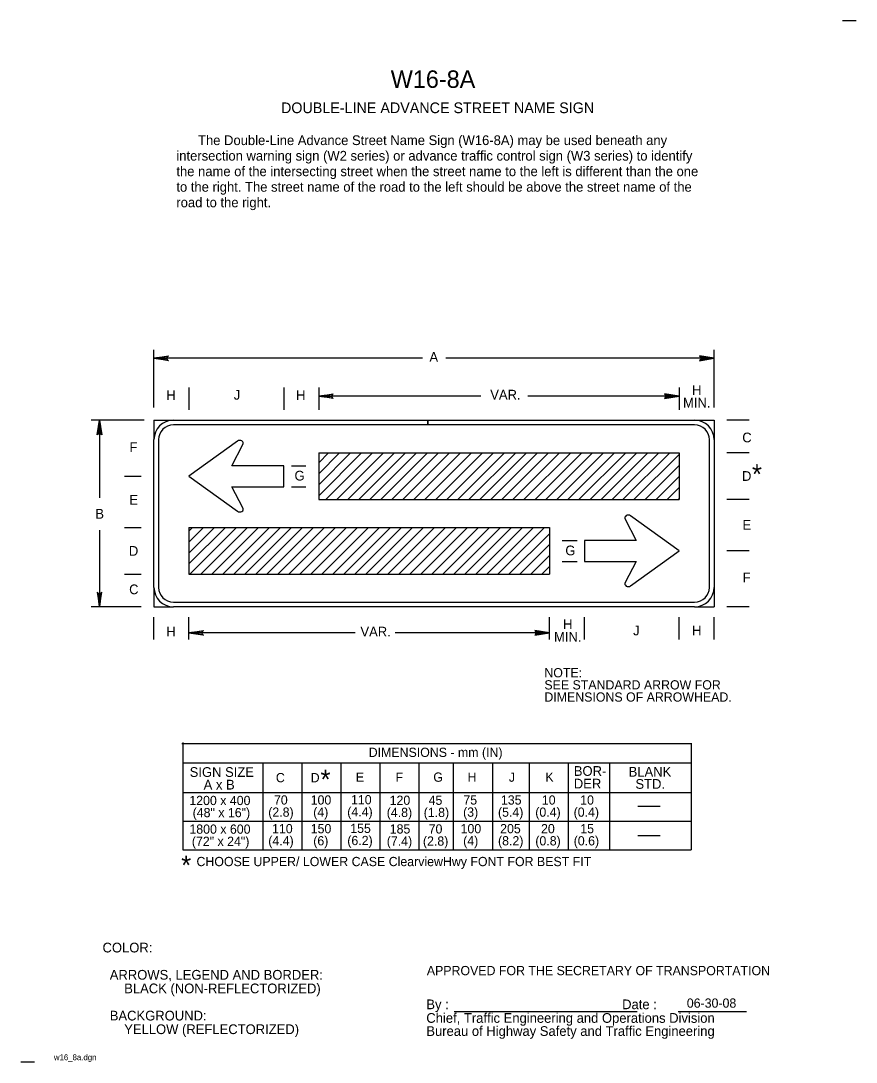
# Model space of a CAD drawing. Extents: x 0.004 to 0.219, y 0.004 to 0.272.
import ezdxf

# ---------------------------------------------------------------- set-up
doc = ezdxf.new("R2010")
doc.units = 0
for name, color, linetype in [('1', 7, 'Continuous'), ('2', 7, 'Continuous'), ('3', 7, 'Continuous'), ('4', 7, 'Continuous'), ('63', 7, 'Continuous')]:
    doc.layers.add(name, color=color, linetype=linetype)

# ---------------------------------------------------------------- blocks, each defined once
blk = doc.blocks.new('RARROW')
at = {"layer": '3'}
for p, q in [((-2.156, 0.285), (-2.2665, 0.384625)), ((-2.2665, 0.384625), (0, 0)), ((0, 0), (-2.2665, -0.379125)), ((-2.156, 0.285), (-2.075625, 0.12075)), ((0, 0), (-2.156, 0.285)), ((-2.14975, -0.2705), (0, 0)), ((-2.075625, 0.12075), (0, 0)), ((0, 0), (-2.074, -0.108)), ((-2.2665, -0.379125), (-2.14975, -0.2705)), ((-2.074, -0.108), (-2.14975, -0.2705))]:
    blk.add_line(p, q, dxfattribs=at)

msp = doc.modelspace()

# ---------------------------------------------------------------- linework, layer by layer
at = {"layer": '1'}
for p, q in [((0.04735, 0.17742), (0.04735, 0.1717)), ((0.0717, 0.17742), (0.0717, 0.1717)), ((0.0807, 0.17742), (0.0807, 0.1717)), ((0.17335, 0.17742), (0.17335, 0.1717)), ((0.02436, 0.16901), (0.02436, 0.14904)), ((0.03835, 0.16901), (0.03835, 0.16401)), ((0.04335, 0.16901), (0.10877, 0.16901)), ((0.10877, 0.16901), (0.10877, 0.16781)), ((0.10877, 0.16781), (0.10877, 0.16901)), ((0.10877, 0.16901), (0.17735, 0.16901)), ((0.18235, 0.16901), (0.18235, 0.16401)), ((0.10877, 0.16781), (0.04335, 0.16781)), ((0.17735, 0.16781), (0.10877, 0.16781)), ((0.03835, 0.12601), (0.03835, 0.16401)), ((0.03955, 0.16401), (0.03955, 0.12601)), ((0.05982, 0.16361), (0.04735, 0.15461)), ((0.18115, 0.12601), (0.18115, 0.16401)), ((0.18235, 0.16401), (0.18235, 0.12601)), ((0.05841, 0.15731), (0.06118, 0.16273)), ((0.0807, 0.16061), (0.0807, 0.14861)), ((0.0807, 0.15806), (0.08325, 0.16061)), ((0.0807, 0.15523), (0.08608, 0.16061)), ((0.0807, 0.1524), (0.08891, 0.16061)), ((0.0807, 0.14957), (0.09174, 0.16061)), ((0.08257, 0.14861), (0.09457, 0.16061)), ((0.08539, 0.14861), (0.09739, 0.16061)), ((0.08822, 0.14861), (0.10022, 0.16061)), ((0.09105, 0.14861), (0.10305, 0.16061)), ((0.09388, 0.14861), (0.10588, 0.16061)), ((0.09671, 0.14861), (0.10871, 0.16061)), ((0.09954, 0.14861), (0.11154, 0.16061)), ((0.10237, 0.14861), (0.11437, 0.16061)), ((0.10519, 0.14861), (0.11719, 0.16061)), ((0.10802, 0.14861), (0.12002, 0.16061)), ((0.11085, 0.14861), (0.12285, 0.16061)), ((0.11368, 0.14861), (0.12568, 0.16061)), ((0.11651, 0.14861), (0.12851, 0.16061)), ((0.11934, 0.14861), (0.13134, 0.16061)), ((0.12216, 0.14861), (0.13416, 0.16061)), ((0.12499, 0.14861), (0.13699, 0.16061)), ((0.12782, 0.14861), (0.13982, 0.16061)), ((0.13065, 0.14861), (0.14265, 0.16061)), ((0.13348, 0.14861), (0.14548, 0.16061)), ((0.13631, 0.14861), (0.14831, 0.16061)), ((0.13913, 0.14861), (0.15113, 0.16061)), ((0.14196, 0.14861), (0.15396, 0.16061)), ((0.14479, 0.14861), (0.15679, 0.16061)), ((0.14762, 0.14861), (0.15962, 0.16061)), ((0.15045, 0.14861), (0.16245, 0.16061)), ((0.15328, 0.14861), (0.16528, 0.16061)), ((0.15611, 0.14861), (0.16811, 0.16061)), ((0.15893, 0.14861), (0.17093, 0.16061)), ((0.16176, 0.14861), (0.17335, 0.1602)), ((0.17335, 0.16061), (0.17335, 0.14861)), ((0.0717, 0.15731), (0.05841, 0.15731)), ((0.0717, 0.15191), (0.0717, 0.15731)), ((0.16459, 0.14861), (0.17335, 0.15737)), ((0.04735, 0.15461), (0.05982, 0.14561)), ((0.16742, 0.14861), (0.17335, 0.15454)), ((0.06118, 0.14648), (0.05841, 0.15191)), ((0.05841, 0.15191), (0.0717, 0.15191)), ((0.17025, 0.14861), (0.17335, 0.15171)), ((0.17308, 0.14861), (0.17335, 0.14888)), ((0.15952, 0.14353), (0.16229, 0.13811)), ((0.17335, 0.13541), (0.16087, 0.14441)), ((0.02436, 0.14074), (0.02436, 0.12101)), ((0.04735, 0.14141), (0.04735, 0.12941)), ((0.04735, 0.14051), (0.04825, 0.14141)), ((0.04735, 0.13768), (0.05108, 0.14141)), ((0.04735, 0.13485), (0.0539, 0.14141)), ((0.04735, 0.13203), (0.05673, 0.14141)), ((0.04756, 0.12941), (0.05956, 0.14141)), ((0.05039, 0.12941), (0.06239, 0.14141)), ((0.05322, 0.12941), (0.06522, 0.14141)), ((0.05605, 0.12941), (0.06805, 0.14141)), ((0.05887, 0.12941), (0.07087, 0.14141)), ((0.0617, 0.12941), (0.0737, 0.14141)), ((0.06453, 0.12941), (0.07653, 0.14141)), ((0.06736, 0.12941), (0.07936, 0.14141)), ((0.07019, 0.12941), (0.08219, 0.14141)), ((0.07302, 0.12941), (0.08502, 0.14141)), ((0.07585, 0.12941), (0.08785, 0.14141)), ((0.07867, 0.12941), (0.09067, 0.14141)), ((0.0815, 0.12941), (0.0935, 0.14141)), ((0.08433, 0.12941), (0.09633, 0.14141)), ((0.08716, 0.12941), (0.09916, 0.14141)), ((0.08999, 0.12941), (0.10199, 0.14141)), ((0.09282, 0.12941), (0.10482, 0.14141)), ((0.09564, 0.12941), (0.10764, 0.14141)), ((0.09847, 0.12941), (0.11047, 0.14141)), ((0.1013, 0.12941), (0.1133, 0.14141)), ((0.10413, 0.12941), (0.11613, 0.14141)), ((0.10696, 0.12941), (0.11896, 0.14141)), ((0.10979, 0.12941), (0.12179, 0.14141)), ((0.11261, 0.12941), (0.12461, 0.14141)), ((0.11544, 0.12941), (0.12744, 0.14141)), ((0.11827, 0.12941), (0.13027, 0.14141)), ((0.1211, 0.12941), (0.1331, 0.14141)), ((0.12393, 0.12941), (0.13593, 0.14141)), ((0.12676, 0.12941), (0.13876, 0.14141)), ((0.12959, 0.12941), (0.14, 0.13982)), ((0.14, 0.14141), (0.14, 0.12941)), ((0.13241, 0.12941), (0.14, 0.137)), ((0.149, 0.13811), (0.149, 0.13271)), ((0.16229, 0.13811), (0.149, 0.13811)), ((0.13524, 0.12941), (0.14, 0.13417)), ((0.16087, 0.12641), (0.17335, 0.13541)), ((0.13807, 0.12941), (0.14, 0.13134)), ((0.149, 0.13271), (0.16229, 0.13271)), ((0.16229, 0.13271), (0.15952, 0.12728)), ((0.03835, 0.12601), (0.03835, 0.12101)), ((0.18235, 0.12601), (0.18235, 0.12101)), ((0.04335, 0.12221), (0.17735, 0.12221)), ((0.17735, 0.12101), (0.04335, 0.12101)), ((0.03835, 0.1126), (0.03835, 0.11832)), ((0.04735, 0.1126), (0.04735, 0.11832)), ((0.14, 0.1126), (0.14, 0.11832)), ((0.149, 0.1126), (0.149, 0.11832)), ((0.17335, 0.1126), (0.17335, 0.11832)), ((0.18235, 0.1126), (0.18235, 0.11832)), ((0.11556, 0.01695), (0.16257, 0.01695)), ((0.17308, 0.01695), (0.19069, 0.01695))]:
    msp.add_line(p, q, dxfattribs=at)
for centre, radius, start, end in [((0.04335, 0.16401), 0.005, 90, 180), ((0.17735, 0.16401), 0.005, 0, 90), ((0.04335, 0.16401), 0.0038, 90, 180), ((0.17735, 0.16401), 0.0038, 0, 90), ((0.04335, 0.12601), 0.005, 180, 270), ((0.04335, 0.12601), 0.0038, 180, 270), ((0.17735, 0.12601), 0.0038, 270, 0), ((0.17735, 0.12601), 0.005, 270, 0)]:
    msp.add_arc(centre, radius, start, end, dxfattribs=at)
for centre, major_axis, start_param, end_param in [((0.06041, 0.16306), (-0.000902, 0), 2.724701, 5.443422), ((0.06041, 0.14616), (-0.000902, 0), 0.839763, 3.558484), ((0.16029, 0.14386), (0.000902, 0), 0.839763, 3.558484), ((0.16029, 0.12696), (0.000902, 0), 2.724701, 5.443422)]:
    msp.add_ellipse(centre, major_axis=major_axis, ratio=0.831622, start_param=start_param, end_param=end_param, dxfattribs=at)
at = {"layer": '3'}
for p, q in [((0.03835, 0.17227), (0.03835, 0.18708)), ((0.10736, 0.18494), (0.03835, 0.18494)), ((0.18235, 0.18494), (0.11335, 0.18494)), ((0.18235, 0.17227), (0.18235, 0.18708)), ((0.12242, 0.17521), (0.0807, 0.17521)), ((0.17335, 0.17521), (0.13443, 0.17521)), ((0.03585, 0.16901), (0.02222, 0.16901)), ((0.03835, 0.16901), (0.04335, 0.16901)), ((0.17735, 0.16901), (0.18235, 0.16901)), ((0.19135, 0.16901), (0.18563, 0.16901)), ((0.0807, 0.16061), (0.17335, 0.16061)), ((0.19135, 0.16061), (0.18563, 0.16061)), ((0.07367, 0.15731), (0.07742, 0.15731)), ((0.03077, 0.15461), (0.03506, 0.15461)), ((0.07367, 0.15191), (0.07742, 0.15191)), ((0.0807, 0.14861), (0.17335, 0.14861)), ((0.19135, 0.14861), (0.18563, 0.14861)), ((0.03077, 0.14141), (0.03506, 0.14141)), ((0.04735, 0.14141), (0.14, 0.14141)), ((0.14328, 0.13811), (0.14712, 0.13811)), ((0.19135, 0.13541), (0.18563, 0.13541)), ((0.14328, 0.13271), (0.14712, 0.13271)), ((0.03077, 0.12941), (0.03506, 0.12941)), ((0.04735, 0.12941), (0.14, 0.12941)), ((0.03506, 0.12101), (0.02222, 0.12101)), ((0.03835, 0.12101), (0.04335, 0.12101)), ((0.17735, 0.12101), (0.18235, 0.12101)), ((0.19135, 0.12101), (0.18563, 0.12101)), ((0.09011, 0.11431), (0.04735, 0.11431)), ((0.14, 0.11431), (0.1004, 0.11431)), ((0.04549, 0.08589), (0.17645, 0.08589)), ((0.04573, 0.08615), (0.04573, 0.05851)), ((0.17645, 0.08596), (0.17645, 0.05851)), ((0.17645, 0.08076), (0.04573, 0.08076)), ((0.06635, 0.08076), (0.06635, 0.05851)), ((0.0864, 0.08076), (0.0864, 0.05851)), ((0.10646, 0.08076), (0.10646, 0.05851)), ((0.11525, 0.08076), (0.11525, 0.05851)), ((0.15543, 0.08076), (0.15543, 0.05851)), ((0.04573, 0.07326), (0.17645, 0.07326)), ((0.16848, 0.06968), (0.16276, 0.06968)), ((0.04574, 0.06589), (0.17645, 0.06589)), ((0.16848, 0.0621), (0.16276, 0.0621)), ((0.04573, 0.05851), (0.17645, 0.05851))]:
    msp.add_line(p, q, dxfattribs=at)
for points in [[(0.07638, 0.08076), (0.07638, 0.05851)], [(0.09643, 0.08076), (0.09643, 0.05851)], [(0.12535, 0.08076), (0.12535, 0.05851)], [(0.1348, 0.08076), (0.1348, 0.05851)], [(0.14484, 0.08076), (0.14484, 0.05851)]]:
    msp.add_lwpolyline(points, dxfattribs=at)
at = {"layer": '63'}
for p, q in [((0.21888, 0.27175), (0.21538, 0.27175)), ((0.00762, 0.00387), (0.00413, 0.00387))]:
    msp.add_line(p, q, dxfattribs=at)

# ---------------------------------------------------------------- block references
at = {"layer": '3', "xscale": 0.0016545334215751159}
for p, yscale, rotation in [((0.03835, 0.18494), 0.0016366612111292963, 180), ((0.0807, 0.17521), 0.0016366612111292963, 180), ((0.02436, 0.16901), 0.0016366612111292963, 89.99999999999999), ((0.02436, 0.12101), -0.0016366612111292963, -89.99999999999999), ((0.04735, 0.11431), 0.0016366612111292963, 180)]:
    msp.add_blockref('RARROW', p, dxfattribs=dict(at, yscale=yscale, rotation=rotation))
at = {"layer": '3', "xscale": 0.0016545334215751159, "yscale": -0.0016366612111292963}
for p in [(0.18235, 0.18494), (0.17335, 0.17521), (0.14, 0.11431)]:
    msp.add_blockref('RARROW', p, dxfattribs=at)

# ---------------------------------------------------------------- texts
at = {"layer": '1'}
for s, height, p in [('W16-8A', 0.0045, (0.09922, 0.2545)), ('DOUBLE-LINE ADVANCE STREET NAME SIGN', 0.0027503, (0.07101, 0.248)), ('CHOOSE UPPER/ LOWER CASE ClearviewHwy FONT FOR BEST FIT', 0.0023752, (0.04928, 0.0543)), ('COLOR:', 0.0025, (0.02513, 0.0321)), ('  ARROWS, LEGEND AND BORDER:', 0.0024998, (0.02513, 0.0251)), ('APPROVED FOR THE SECRETARY OF TRANSPORTATION', 0.0023752, (0.1085, 0.02625)), ('      BLACK (NON-REFLECTORIZED)', 0.0024998, (0.02513, 0.0216)), ('By :                                                Date :', 0.0024998, (0.10837, 0.0175)), ('  BACKGROUND:', 0.0024998, (0.02513, 0.0146)), ('Chief, Traffic Engineering and Operations Division', 0.0024998, (0.10837, 0.014)), ('      YELLOW (REFLECTORIZED)', 0.0024998, (0.02513, 0.0111)), ('Bureau of Highway Safety and Traffic Engineering', 0.0024998, (0.10837, 0.01063)), ('w16_8a.dgn', 0.0015, (0.01263, 0.00438))]:
    msp.add_text(s, height=height, dxfattribs=at).set_placement(p)
at = {"layer": '2'}
for s, p in [('      The Double-Line Advance Street Name Sign (W16-8A) may be used beneath any', (0.04411, 0.23979)), ('intersection warning sign (W2 series) or advance traffic control sign (W3 series) to identify', (0.04411, 0.23579)), ('the name of the intersecting street when the street name to the left is different than the one', (0.04411, 0.23179)), ('to the right. The street name of the road to the left should be above the street name of the', (0.04411, 0.22779)), ('road to the right.', (0.04411, 0.22379))]:
    msp.add_text(s, height=0.0024998, dxfattribs=at).set_placement(p)
at = {"layer": '3'}
for s, height, p in [('A', 0.0025, (0.10917, 0.18405)), ('VAR.', 0.0025, (0.1248, 0.17433)), ('H', 0.0025, (0.17669, 0.17552)), ('H', 0.0025, (0.04154, 0.17419)), ('J', 0.0025, (0.05886, 0.17429)), ('H', 0.0025, (0.07489, 0.17419)), ('MIN.', 0.0025, (0.17437, 0.17227)), ('C', 0.0025, (0.1896, 0.16332)), ('F', 0.0025, (0.03206, 0.16085)), ('D', 0.0025, (0.18953, 0.15341)), ('*', 0.00493, (0.19209, 0.15269)), ('E', 0.0025, (0.03203, 0.14731)), ('B', 0.0025, (0.02328, 0.14369)), ('E', 0.0025, (0.18966, 0.14083)), ('D', 0.0025, (0.0319, 0.13415)), ('G', 0.0025, (0.14411, 0.13426)), ('F', 0.0025, (0.1897, 0.12729)), ('C', 0.0025, (0.03197, 0.12425)), ('H', 0.0025, (0.04154, 0.11338)), ('VAR.', 0.0025, (0.09143, 0.11338)), ('H', 0.0025, (0.14352, 0.11529)), ('J', 0.0025, (0.16152, 0.11367)), ('H', 0.0025, (0.17669, 0.11367)), ('MIN.', 0.0025, (0.1412, 0.11204)), ('NOTE:', 0.002375, (0.13872, 0.10287)), ('SEE STANDARD ARROW FOR', 0.0023752, (0.13872, 0.09975)), ('DIMENSIONS OF ARROWHEAD.', 0.0023752, (0.13872, 0.09662)), ('DIMENSIONS - mm (IN)', 0.0023752, (0.09356, 0.08239)), ('SIGN SIZE', 0.0025, (0.04753, 0.07726)), ('C', 0.00238, (0.06969, 0.07588)), ('D', 0.00238, (0.07864, 0.07587)), ('*', 0.00493, (0.08117, 0.07418)), ('F', 0.00238, (0.10046, 0.07601)), ('G', 0.00238, (0.11017, 0.07601)), ('H', 0.00238, (0.11897, 0.07601)), ('J', 0.00238, (0.12959, 0.07601)), ('K', 0.00238, (0.13899, 0.07601)), ('BOR-', 0.0025, (0.14629, 0.07753)), ('BLANK', 0.0025, (0.16038, 0.07733)), ('A x B', 0.0025, (0.05112, 0.07401)), ('DER', 0.0025, (0.14629, 0.07428)), ('STD.', 0.0025, (0.16213, 0.0742)), ('1200 x 400', 0.002375, (0.04744, 0.07001)), ('70', 0.002375, (0.0692, 0.07014)), ('100', 0.002375, (0.07864, 0.07014)), ('110', 0.002375, (0.08901, 0.07021)), ('120', 0.002375, (0.09894, 0.07007)), ('45', 0.002375, (0.10896, 0.07007)), ('75', 0.002375, (0.1179, 0.07014)), ('135', 0.002375, (0.12755, 0.07014)), ('10', 0.002375, (0.13807, 0.07013)), ('10', 0.002375, (0.14793, 0.07013)), ('(48" x 16")', 0.0023752, (0.04829, 0.06689)), ('(2.8)', 0.002375, (0.06773, 0.06701)), ('(4)', 0.002375, (0.07929, 0.06701)), ('(4.4)', 0.002375, (0.08804, 0.06709)), ('(4.8)', 0.002375, (0.09819, 0.06694)), ('(1.8)', 0.002375, (0.1077, 0.06694)), ('(3)', 0.002375, (0.11782, 0.06701)), ('(5.4)', 0.002375, (0.12679, 0.06701)), ('(0.4)', 0.002375, (0.13638, 0.06701)), ('(0.4)', 0.002375, (0.14624, 0.06701)), ('1800 x 600', 0.002375, (0.04746, 0.06264)), ('110', 0.002375, (0.06871, 0.06276)), ('150', 0.002375, (0.07865, 0.06276)), ('155', 0.002375, (0.08881, 0.06284)), ('185', 0.002375, (0.09896, 0.06269)), ('70', 0.002375, (0.10897, 0.06269)), ('100', 0.002375, (0.11718, 0.06276)), ('205', 0.002375, (0.12735, 0.06276)), ('20', 0.002375, (0.13786, 0.06276)), ('15', 0.002375, (0.14795, 0.06276)), ('(72" x 24")', 0.0023752, (0.04809, 0.05951)), ('(4.4)', 0.002375, (0.06774, 0.05964)), ('(6)', 0.002375, (0.0793, 0.05964)), ('(6.2)', 0.002375, (0.08805, 0.05971)), ('(7.4)', 0.002375, (0.0982, 0.05957)), ('(2.8)', 0.002375, (0.1075, 0.05957)), ('(4)', 0.002375, (0.11784, 0.05964)), ('(8.2)', 0.002375, (0.1268, 0.05964)), ('(0.8)', 0.002375, (0.13639, 0.05963)), ('(0.6)', 0.002375, (0.14626, 0.05963)), ('*', 0.00493, (0.04535, 0.0521))]:
    msp.add_text(s, height=height, dxfattribs=at).set_placement(p)
for s, height, p in [('G', 0.0025, (0.07448, 0.1535)), ('E', 0.00238, (0.09024, 0.07601))]:
    msp.add_text(s, height=height, rotation=360, dxfattribs=at).set_placement(p)
at = {"layer": '4'}
msp.add_text('06-30-08', height=0.002375, dxfattribs=at).set_placement((0.17534, 0.01789))

doc.saveas('drawing.dxf')
